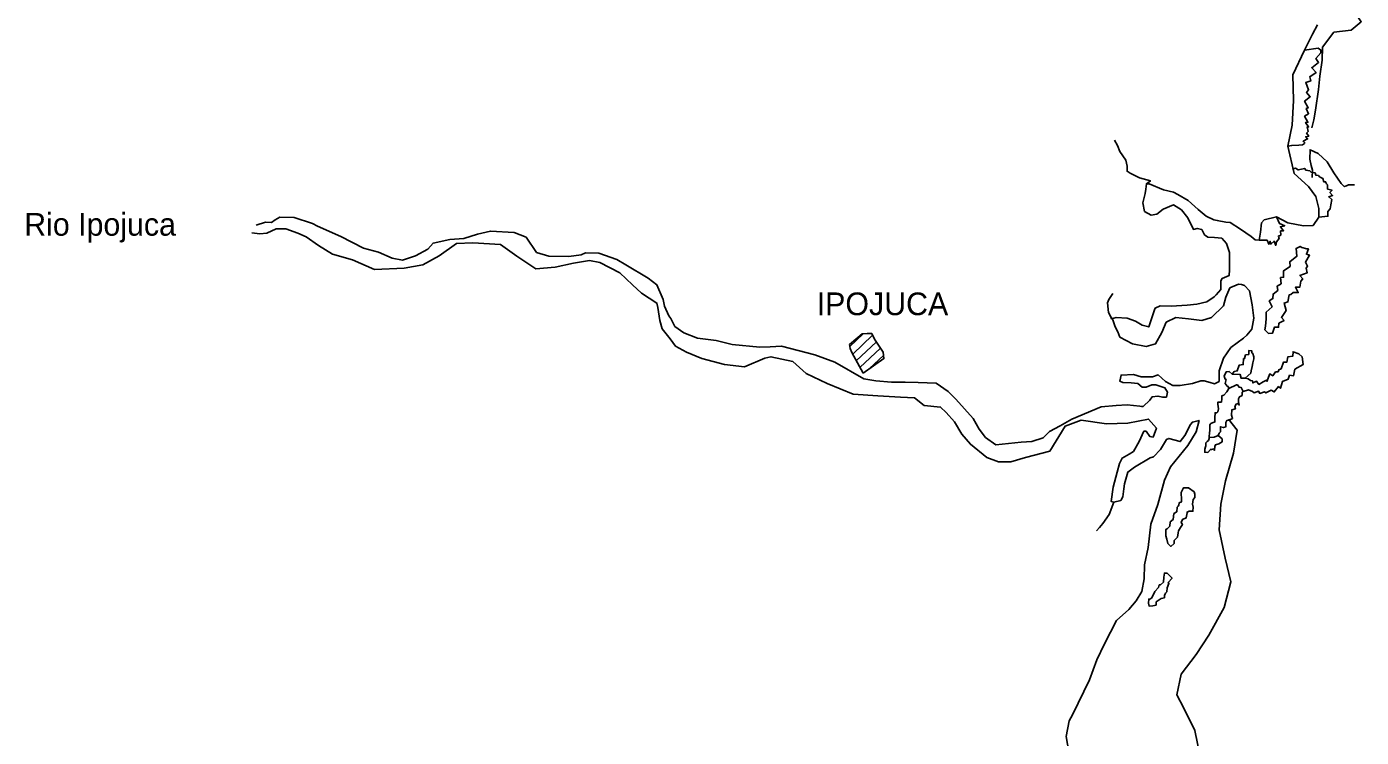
# Model space of a CAD drawing. Extents: x 662444 to 1640468, y 7452018 to 9606170.
# Drawn here: x 1573864 to 1614210, y 9045876 to 9067368 of the extents above; entities that cross this region are included whole.
import ezdxf

# ---------------------------------------------------------------- set-up
doc = ezdxf.new("R2010")
doc.units = 0
doc.layers.add('Level 1', color=7, linetype='Continuous')
doc.layers.add('Level 3', color=7, linetype='Continuous')

msp = doc.modelspace()

# ---------------------------------------------------------------- linework, layer by layer
at = {"layer": 'Level 1'}
for points in [[(1613744, 9072355), (1613688, 9071909), (1613508, 9070805), (1613315, 9069939), (1613082, 9069153), (1612924, 9068888), (1612918, 9068514), (1613138, 9068185), (1613459, 9068016), (1613820, 9067855), (1614060, 9067729), (1614210, 9067515), (1613906, 9067260), (1613380, 9067204), (1613041, 9066747), (1613025, 9066356), (1612952, 9065870), (1612920, 9065463), (1612829, 9064847), (1612775, 9064547), (1612714, 9064312)], [(1606641, 9058595), (1606657, 9058537), (1606803, 9058576), (1607134, 9058554), (1607383, 9058460), (1607582, 9058342), (1607783, 9058290), (1607963, 9058800), (1607980, 9058855), (1608126, 9058927), (1608458, 9058913), (1608950, 9058945), (1609234, 9058972), (1609542, 9059049), (1609763, 9059199), (1609821, 9059263), (1609961, 9059423), (1609963, 9059521), (1609966, 9059683), (1609999, 9059755), (1610211, 9059842), (1610223, 9060012), (1610224, 9060118), (1610224, 9060541), (1610139, 9060811), (1609989, 9060976), (1609770, 9060996), (1609569, 9060999), (1609465, 9061075), (1609387, 9061239), (1609251, 9061266), (1609137, 9061235), (1608965, 9061588), (1608775, 9061827), (1608535, 9061977), (1608218, 9061853), (1608029, 9061694), (1607860, 9061672), (1607651, 9061781), (1607608, 9062042), (1607678, 9062326), (1607696, 9062455), (1607714, 9062618), (1607796, 9062617), (1608229, 9062438), (1608534, 9062360), (1608662, 9062293), (1608975, 9062108), (1609277, 9061842), (1609524, 9061635), (1609748, 9061525), (1609853, 9061507), (1610119, 9061453), (1610247, 9061443), (1610560, 9061242), (1610878, 9061025), (1611005, 9060925), (1611119, 9060908), (1611163, 9061150), (1611193, 9061435), (1611275, 9061531), (1611648, 9061622), (1611993, 9061438), (1612460, 9061348), (1612751, 9061359), (1612925, 9061608), (1612930, 9061868), (1612840, 9062236), (1612610, 9062532), (1612181, 9062923), (1611993, 9063755), (1612118, 9064388), (1612164, 9065136), (1612145, 9065916), (1612489, 9066659), (1612732, 9067142), (1612890, 9067424)], [(1611993, 9063755), (1612107, 9063778), (1612317, 9063782), (1612430, 9063797), (1612496, 9063836), (1612497, 9063868), (1612449, 9063902), (1612587, 9063973), (1612532, 9064039), (1612621, 9064054), (1612558, 9064152), (1612607, 9064200), (1612577, 9064339), (1612617, 9064338), (1612524, 9064471), (1612596, 9064476), (1612495, 9064658), (1612617, 9064736), (1612547, 9064892), (1612604, 9064916), (1612494, 9065114), (1612667, 9065248), (1612556, 9065373), (1612614, 9065461), (1612529, 9065682), (1612683, 9065727), (1612653, 9065851), (1612841, 9065977), (1612714, 9066126), (1612919, 9066285), (1612840, 9066401), (1612989, 9066576), (1612990, 9066658), (1612910, 9066717), (1612489, 9066659)], [(1607714, 9062618), (1607837, 9062704), (1607507, 9062792), (1607227, 9062936), (1607131, 9062994), (1607134, 9063148), (1607088, 9063328), (1606907, 9063592), (1606838, 9063771), (1606752, 9063936)], [(1612720, 9062807), (1612733, 9063027), (1612695, 9063166), (1612657, 9063361), (1612662, 9063646), (1612911, 9063536), (1613181, 9063279), (1613377, 9062951), (1613598, 9062629), (1613693, 9062530), (1613758, 9062553), (1613824, 9062584), (1614009, 9062582)], [(1612126, 9063061), (1612216, 9063085), (1612304, 9063034), (1612499, 9063080), (1612530, 9063031), (1612652, 9063012), (1612691, 9062963), (1612812, 9062944), (1612835, 9062878), (1612915, 9062869), (1612947, 9062828), (1613043, 9062777), (1613074, 9062679), (1613131, 9062678), (1613154, 9062613), (1613185, 9062587), (1613191, 9062458), (1613328, 9062423), (1613262, 9062351), (1613341, 9062260), (1613227, 9062221), (1613315, 9062138), (1613287, 9061976), (1613270, 9061862), (1613203, 9061782), (1613200, 9061636), (1612925, 9061608)], [(1580796, 9061369), (1581087, 9061454), (1581265, 9061450), (1581372, 9061529), (1581518, 9061609), (1581954, 9061601), (1582508, 9061413), (1582660, 9061338), (1583357, 9061025), (1584045, 9060672), (1584504, 9060551), (1584913, 9060364), (1585226, 9060303), (1585616, 9060434), (1585991, 9060639), (1586148, 9060824), (1586658, 9060936), (1587079, 9060963), (1587493, 9061094), (1587882, 9061185), (1588600, 9061148), (1588961, 9061004), (1589277, 9060543), (1589646, 9060423), (1590251, 9060413), (1590624, 9060464), (1590761, 9060526), (1591158, 9060520), (1591703, 9060331), (1591975, 9060164), (1592654, 9059762), (1592918, 9059563), (1593104, 9059112), (1593149, 9058916), (1593281, 9058622), (1593336, 9058540), (1593461, 9058301), (1593732, 9058110), (1594142, 9057948), (1594706, 9057882), (1595189, 9057760), (1596027, 9057680), (1596342, 9057683), (1596682, 9057701), (1597686, 9057440), (1598297, 9057218), (1599168, 9056715), (1599531, 9056661), (1600006, 9056620), (1600160, 9056617), (1600418, 9056612), (1600814, 9056606), (1601354, 9056588), (1601722, 9056330), (1601952, 9056098), (1602475, 9055520), (1602656, 9055191), (1602853, 9054945), (1603163, 9054719), (1603924, 9054804), (1604248, 9054822), (1604590, 9054938), (1604779, 9055122), (1605104, 9055295), (1605464, 9055500), (1606343, 9055867), (1606804, 9055908), (1607127, 9055927), (1607514, 9055888), (1607571, 9055878), (1607611, 9055877), (1607817, 9056077), (1607884, 9056173), (1608061, 9056195), (1608207, 9056159), (1608320, 9056167), (1608355, 9056312), (1608275, 9056443), (1608003, 9056537), (1607873, 9056540), (1607710, 9056462), (1607582, 9056464), (1607454, 9056572), (1607253, 9056599), (1607003, 9056604), (1606914, 9056646), (1606949, 9056833), (1607322, 9056850), (1607555, 9056781), (1607781, 9056778), (1607902, 9056775), (1608073, 9056838), (1608287, 9056638), (1608511, 9056521), (1608738, 9056516), (1609103, 9056575), (1609354, 9056661), (1609459, 9056658), (1609645, 9056606), (1609773, 9056571), (1609912, 9056642)], [(1611648, 9061622), (1611734, 9061417), (1611894, 9061349), (1611765, 9061319), (1611859, 9061195), (1611770, 9061189), (1611776, 9061067), (1611703, 9061035), (1611725, 9060962), (1611643, 9060866), (1611625, 9060752), (1611571, 9060884), (1611480, 9060787), (1611457, 9060878), (1611416, 9060789), (1611362, 9060912), (1611119, 9060908)], [(1593807, 9057520), (1593481, 9057707), (1593316, 9057930), (1593073, 9058228), (1593006, 9058481), (1592944, 9058872), (1592915, 9059011), (1592445, 9059307), (1592175, 9059565), (1591797, 9059923), (1591190, 9060240), (1590875, 9060297), (1590396, 9060220), (1589835, 9060097), (1589260, 9060047), (1588679, 9060428), (1588186, 9060780), (1587354, 9060827), (1586860, 9060807), (1586334, 9060440), (1585842, 9060169), (1585273, 9060062), (1584375, 9060029), (1583718, 9060314), (1583108, 9060484), (1582685, 9060746), (1582312, 9061008), (1582056, 9061127), (1581694, 9061250), (1581404, 9061250), (1581126, 9061127), (1580915, 9061101), (1580674, 9061131)], [(1612560, 9060646), (1612610, 9060646), (1612550, 9060484), (1612646, 9060457), (1612521, 9060248), (1612584, 9060126), (1612542, 9060062), (1612572, 9059923), (1612352, 9059845), (1612440, 9059745), (1612382, 9059674), (1612354, 9059495), (1612216, 9059489), (1612303, 9059325), (1612150, 9059328), (1612083, 9059264), (1612027, 9059257), (1611990, 9059046), (1611877, 9059007), (1611938, 9058787), (1611797, 9058577), (1611876, 9058486), (1611713, 9058400), (1611711, 9058278), (1611589, 9058281), (1611530, 9058102), (1611400, 9058089), (1611297, 9058196), (1611315, 9058310), (1611335, 9058529), (1611330, 9058732), (1611511, 9058892), (1611425, 9059072), (1611540, 9059143), (1611542, 9059281), (1611682, 9059393), (1611668, 9059524), (1611791, 9059595), (1611770, 9059782), (1611858, 9059788), (1611862, 9059984), (1612058, 9060119), (1612045, 9060257), (1612266, 9060423), (1612238, 9060660), (1612360, 9060723), (1612408, 9060689), (1612560, 9060646)], [(1609912, 9056642), (1609917, 9056959), (1610045, 9057339), (1610269, 9057669), (1610653, 9057946), (1610753, 9058035), (1610901, 9058220), (1610964, 9058552), (1610914, 9058951), (1610833, 9059376), (1610682, 9059540), (1610586, 9059575), (1610498, 9059584), (1610236, 9059467), (1610111, 9059192), (1610041, 9058926), (1609679, 9058574), (1609387, 9058481), (1608991, 9058529), (1608604, 9058577), (1608311, 9058427), (1608177, 9058120), (1607992, 9057774), (1607709, 9057698), (1607290, 9057778), (1606913, 9057980), (1606852, 9058143), (1606766, 9058292), (1606696, 9058504), (1606641, 9058595), (1606563, 9058726), (1606536, 9059019), (1606578, 9059116), (1606702, 9059301)], [(1599147, 9056886), (1598810, 9057510), (1598757, 9057634), (1598742, 9057755), (1599119, 9058075), (1599273, 9058088), (1599411, 9058085), (1599496, 9057921), (1599755, 9057526), (1599777, 9057332), (1599147, 9056886)], [(1598749, 9057696), (1599149, 9058077)], [(1598834, 9057467), (1599434, 9058040)], [(1598944, 9057262), (1599550, 9057840)], [(1605403, 9045267), (1605290, 9045902), (1605375, 9046371), (1605477, 9046554), (1605989, 9047611), (1606215, 9048221), (1606446, 9048702), (1606812, 9049405), (1607185, 9049743), (1607402, 9050005), (1607579, 9050284), (1607645, 9050672), (1607656, 9051093), (1607767, 9051617), (1607850, 9052321), (1608059, 9052915), (1608256, 9053655), (1608444, 9054056), (1608970, 9054699), (1609216, 9055114), (1609306, 9055461), (1609102, 9055409), (1609044, 9055337), (1608873, 9055009), (1608739, 9054818), (1608394, 9054917), (1608320, 9054887), (1608142, 9054576), (1607926, 9054362), (1607828, 9054324), (1607351, 9054045), (1607154, 9053896), (1607056, 9053542), (1607027, 9053389), (1607005, 9053154), (1606937, 9053034), (1606726, 9052983), (1606646, 9053010), (1606705, 9053438), (1606830, 9053897), (1606901, 9054154), (1606979, 9054323), (1607192, 9054439), (1607324, 9054524), (1607493, 9054819), (1607639, 9055132), (1607704, 9055138), (1607813, 9054974), (1607917, 9054954), (1608014, 9055227), (1607777, 9055501), (1607151, 9055373), (1606503, 9055357), (1605737, 9055466), (1605255, 9055286), (1604792, 9054535), (1604058, 9054336), (1603617, 9054210), (1603245, 9054204), (1602893, 9054343), (1602393, 9054737), (1602134, 9055044), (1601909, 9055416), (1601665, 9055697), (1601491, 9055864), (1600999, 9055909), (1600706, 9056145), (1600277, 9056164), (1599591, 9056199), (1598848, 9056251), (1598063, 9056572), (1597432, 9056881), (1597020, 9057240), (1596361, 9057387), (1596181, 9057344), (1595559, 9057076), (1594963, 9057148), (1594271, 9057330), (1593807, 9057520)], [(1599054, 9057058), (1599675, 9057650)], [(1599347, 9057028), (1599766, 9057428)], [(1610207, 9056425), (1610184, 9056483), (1610152, 9056500), (1610096, 9056574), (1610122, 9056696), (1610098, 9056712), (1610060, 9056802), (1610127, 9056932), (1610216, 9056938), (1610311, 9056855), (1610546, 9056851), (1610576, 9056737), (1610697, 9056734), (1610786, 9056717), (1610865, 9056667), (1610922, 9056657), (1610929, 9056592), (1611042, 9056647), (1611114, 9056548), (1611244, 9056628), (1611343, 9056674), (1611358, 9056641), (1611443, 9056867), (1611531, 9056809), (1611621, 9056930), (1611694, 9056928), (1611720, 9056993), (1611785, 9057025), (1611853, 9057218), (1611958, 9057217), (1611993, 9057386), (1612139, 9057401), (1612150, 9057538), (1612326, 9057470), (1612421, 9057379), (1612450, 9057151), (1612197, 9057009), (1612160, 9056806), (1612040, 9056825), (1611998, 9056704), (1611826, 9056633), (1611766, 9056431), (1611710, 9056481), (1611579, 9056320), (1611483, 9056371), (1611327, 9056292), (1611288, 9056326), (1611141, 9056279), (1611102, 9056345), (1610972, 9056299), (1610924, 9056339), (1610795, 9056383), (1610642, 9056337), (1610626, 9056353), (1610579, 9056452), (1610514, 9056461), (1610467, 9056535), (1610435, 9056535), (1610207, 9056425)], [(1610311, 9056855), (1610369, 9056943), (1610459, 9056958), (1610518, 9057136), (1610640, 9057150), (1610651, 9057329), (1610683, 9057328), (1610710, 9057442), (1610807, 9057456), (1610809, 9057570), (1610897, 9057569), (1610905, 9057503), (1610929, 9057479), (1610959, 9057388), (1610966, 9057323), (1610932, 9057202), (1610913, 9057089), (1610878, 9056959), (1610870, 9056894), (1610697, 9056734)], [(1610642, 9056337), (1610609, 9056313), (1610606, 9056215), (1610525, 9056176), (1610500, 9056111), (1610499, 9056023), (1610521, 9055924), (1610489, 9055973), (1610424, 9055950), (1610391, 9055877), (1610406, 9055813), (1610300, 9055782), (1610281, 9055619), (1610320, 9055521), (1610214, 9055466), (1610149, 9055459), (1610116, 9055395), (1610113, 9055265), (1610040, 9055242), (1609951, 9055268), (1609949, 9055113), (1609916, 9055072), (1609882, 9055008), (1609947, 9054958), (1610002, 9054900), (1610000, 9054810), (1609902, 9054748), (1609804, 9054725), (1609779, 9054668), (1609770, 9054555), (1609754, 9054603), (1609681, 9054581), (1609648, 9054582), (1609574, 9054492), (1609477, 9054495), (1609479, 9054593), (1609496, 9054657), (1609514, 9054689), (1609515, 9054787), (1609548, 9054819), (1609588, 9054850), (1609614, 9054915), (1609614, 9054947), (1609760, 9054954), (1609882, 9055008)], [(1609614, 9054947), (1609615, 9054997), (1609625, 9055054), (1609627, 9055184), (1609630, 9055330), (1609663, 9055362), (1609785, 9055417), (1609787, 9055538), (1609790, 9055693), (1609838, 9055692), (1609871, 9055715), (1609888, 9055813), (1609875, 9055951), (1609877, 9056016), (1609949, 9056015), (1609981, 9056015), (1609991, 9056112), (1609992, 9056202), (1610050, 9056225), (1610148, 9056321), (1610207, 9056425)], [(1610199, 9055498), (1610459, 9055169), (1610350, 9054471), (1610108, 9053638), (1609967, 9052925), (1609912, 9052153), (1610099, 9051296), (1610263, 9050577), (1610064, 9049800), (1609596, 9048970), (1609214, 9048384), (1608767, 9047789), (1608635, 9047166), (1608846, 9046763), (1609180, 9046082), (1609417, 9044899)], [(1609157, 9053305), (1609180, 9053232), (1609179, 9053167), (1609178, 9053134), (1609128, 9053069), (1609102, 9052932), (1609125, 9052841), (1609122, 9052712), (1609010, 9052714), (1608944, 9052690), (1608944, 9052666), (1608917, 9052512), (1608803, 9052466), (1608768, 9052377), (1608800, 9052311), (1608742, 9052222), (1608684, 9052125), (1608674, 9052060), (1608656, 9051930), (1608557, 9051828), (1608555, 9051738), (1608449, 9051650), (1608362, 9051741), (1608331, 9051872), (1608302, 9051970), (1608304, 9052165), (1608337, 9052180), (1608420, 9052260), (1608430, 9052390), (1608520, 9052462), (1608539, 9052641), (1608629, 9052696), (1608648, 9052833), (1608673, 9052866), (1608697, 9052898), (1608699, 9052963), (1608772, 9052994), (1608773, 9053092), (1608761, 9053247), (1608760, 9053280), (1608836, 9053425), (1608990, 9053422), (1609157, 9053305)], [(1606726, 9052983), (1606592, 9052618), (1606393, 9052345), (1606294, 9052224), (1606204, 9052121)], [(1608007, 9049975), (1608005, 9049877), (1607908, 9049854), (1607802, 9049840), (1607780, 9049938), (1607782, 9050059), (1607815, 9050059), (1607879, 9050090), (1607972, 9050284), (1608079, 9050412), (1608104, 9050485), (1608137, 9050484), (1608227, 9050564), (1608238, 9050719), (1608257, 9050841), (1608337, 9050838), (1608489, 9050690), (1608372, 9050561), (1608396, 9050528), (1608338, 9050399), (1608327, 9050277), (1608295, 9050238), (1608260, 9050164), (1608260, 9050099), (1608162, 9050077), (1608007, 9049975)]]:
    msp.add_lwpolyline(points, dxfattribs=at)

# ---------------------------------------------------------------- texts
at = {"layer": 'Level 3'}
for s, height, p in [('Rio Ipojuca', 685.51, (1573789, 9061047)), ('IPOJUCA', 685.9, (1597747, 9058643))]:
    msp.add_text(s, height=height, dxfattribs=at).set_placement(p)

doc.saveas('drawing.dxf')
